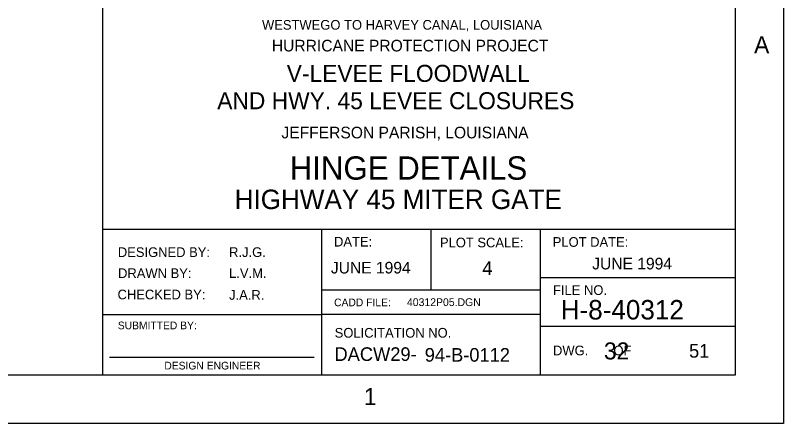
# Model space of a CAD drawing. Extents: x 0 to 13.6, y 0 to 9.6.
# Drawn here: x 10.825 to 13.458, y 0.125 to 1.526 of the extents above; entities that cross this region are included whole.
import ezdxf

# ---------------------------------------------------------------- set-up
doc = ezdxf.new("R2010")
doc.units = 0
doc.layers.add('Level 1', color=7, linetype='Continuous')
doc.layers.add('Level 2', color=7, linetype='Continuous')

msp = doc.modelspace()

# ---------------------------------------------------------------- linework, layer by layer
at = {"layer": 'Level 1'}
for p, q in [((11.125, 0.2917), (11.125, 1.875)), ((13.2917, 0.7917), (11.125, 0.7917)), ((11.875, 0.2917), (11.875, 0.7917)), ((12.25, 0.5833), (12.25, 0.7917)), ((12.625, 0.2917), (12.625, 0.7917)), ((13.2917, 0.625), (12.625, 0.625)), ((12.625, 0.5833), (11.875, 0.5833)), ((11.125, 0.5), (11.875, 0.5)), ((12.625, 0.5), (11.875, 0.5)), ((13.2917, 0.4583), (12.625, 0.4583)), ((11.1474, 0.3528), (11.8484, 0.3528))]:
    msp.add_line(p, q, dxfattribs=at)
for points in [[(0.125, 9.4583), (13.4583, 9.4583), (13.4583, 0.125), (0.125, 0.125)], [(0.625, 9.2917), (13.2917, 9.2917), (13.2917, 0.2917), (0.625, 0.2917)]]:
    msp.add_lwpolyline(points, close=True, dxfattribs=at)

# ---------------------------------------------------------------- texts
for s, height, p in [('A', 0.0584, (13.3571, 1.3961)), ('DATE:', 0.03321, (11.917, 0.7329)), ('PLOT DATE:', 0.03321, (12.6668, 0.7319)), ('PLOT SCALE:', 0.033208, (12.2802, 0.73)), ('DESIGNED BY:', 0.033208, (11.176, 0.6969)), ('DRAWN BY:', 0.03321, (11.1767, 0.6247)), ('CHECKED BY:', 0.033208, (11.175, 0.5516)), ('FILE NO.', 0.03321, (12.6678, 0.5667)), ('CADD FILE:', 0.02642, (11.9173, 0.5278)), ('SUBMITTED BY:', 0.026417, (11.1758, 0.4489)), ('SOLICITATION NO.', 0.033208, (11.9193, 0.4202)), ('DACW29-', 0.04679, (11.9187, 0.3402)), ('DWG.       OF', 0.033208, (12.6678, 0.3595)), ('DESIGN ENGINEER', 0.026417, (11.3353, 0.3109)), ('1', 0.0584, (12.0192, 0.1887))]:
    msp.add_text(s, height=height, dxfattribs=at).set_placement(p)
at = {"layer": 'Level 2'}
for s, height, p in [('WESTWEGO TO HARVEY CANAL, LOUISIANA', 0.033208, (11.6702, 1.477)), ('HURRICANE PROTECTION PROJECT', 0.04, (11.7039, 1.4023)), ('V-LEVEE FLOODWALL', 0.058417, (11.7549, 1.2979)), ('AND HWY. 45 LEVEE CLOSURES', 0.058417, (11.5167, 1.2041)), ('JEFFERSON PARISH, LOUISIANA', 0.04, (11.7368, 1.104)), ('HINGE DETAILS', 0.08, (11.7651, 0.9623)), ('HIGHWAY 45 MITER GATE', 0.066792, (11.5765, 0.8614)), ('R.J.G.', 0.03321, (11.5573, 0.697)), ('JUNE 1994', 0.04, (12.8021, 0.6543)), ('JUNE 1994', 0.04, (11.9062, 0.6403)), ('4', 0.0468, (12.4254, 0.6354)), ('L.V.M.', 0.03321, (11.5573, 0.6252)), ('J.A.R.', 0.03321, (11.5573, 0.5502)), ('40312P05.DGN', 0.026792, (12.1671, 0.5285)), ('H-8-40312', 0.06679, (12.6942, 0.4825)), ('32', 0.05842, (12.8423, 0.3454)), ('51', 0.04679, (13.1341, 0.3515)), ('94-B-0112', 0.04679, (12.228, 0.3377))]:
    msp.add_text(s, height=height, dxfattribs=at).set_placement(p)

doc.saveas('drawing.dxf')
